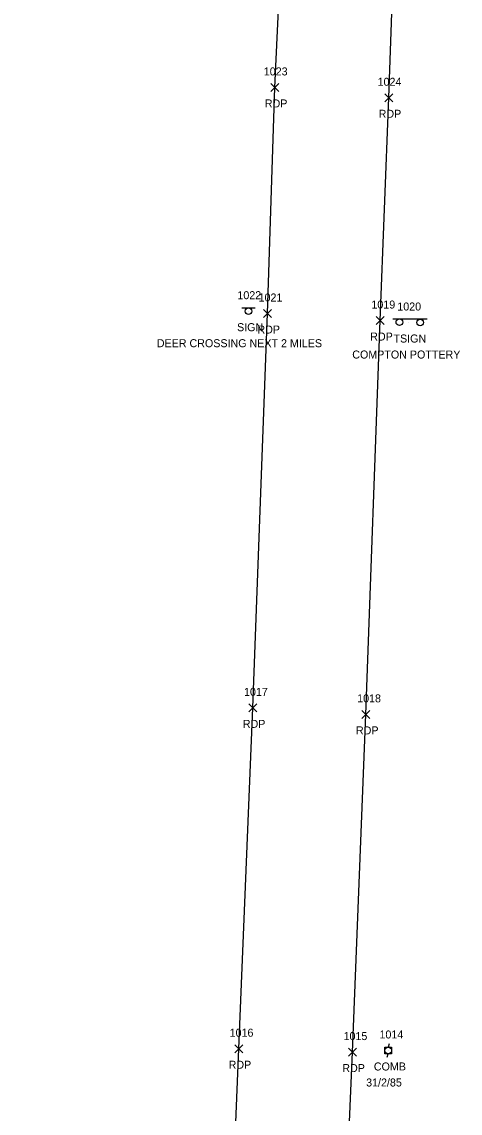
# Model space of a CAD drawing. Extents: x 1496556 to 1498241, y 599216 to 604470.
# Drawn here: x 1497213.5 to 1497323.1, y 602108 to 602380.7 of the extents above; entities that cross this region are included whole.
import ezdxf

# ---------------------------------------------------------------- set-up
doc = ezdxf.new("R2010")
doc.units = 0
for name, color, linetype in [('P_A', 7, 'Continuous'), ('P_I', 7, 'Continuous'), ('P_TIC', 7, 'Continuous'), ('PET', 7, 'Continuous'), ('S_A', 7, 'Continuous'), ('S_C', 7, 'Continuous'), ('S_I', 7, 'Continuous'), ('SSGN', 7, 'Continuous'), ('U_A', 7, 'Continuous'), ('U_C', 7, 'Continuous'), ('U_I', 7, 'Continuous'), ('UP', 7, 'Continuous')]:
    doc.layers.add(name, color=color, linetype=linetype)

msp = doc.modelspace()

# ---------------------------------------------------------------- linework, layer by layer
at = {"layer": 'P_TIC'}
for points in [[(1497275.81, 602363.31), (1497277.81, 602365.31)], [(1497277.81, 602363.31), (1497275.81, 602365.31)], [(1497304.27, 602360.72), (1497306.27, 602362.72)], [(1497306.27, 602360.72), (1497304.27, 602362.72)], [(1497273.95, 602306.82), (1497275.95, 602308.82)], [(1497275.95, 602306.82), (1497273.95, 602308.82)], [(1497302.16, 602305.06), (1497304.16, 602307.06)], [(1497304.16, 602305.06), (1497302.16, 602307.06)], [(1497270.3, 602208.29), (1497272.3, 602210.29)], [(1497272.3, 602208.29), (1497270.3, 602210.29)], [(1497298.59, 602206.66), (1497300.59, 602208.66)], [(1497300.59, 602206.66), (1497298.59, 602208.66)], [(1497266.76, 602123.12), (1497268.76, 602125.12)], [(1497268.76, 602123.12), (1497266.76, 602125.12)], [(1497295.19, 602122.28), (1497297.19, 602124.28)], [(1497297.19, 602122.28), (1497295.19, 602124.28)]]:
    msp.add_lwpolyline(points, dxfattribs=at)
at = {"layer": 'PET'}
for points in [[(1497255.35, 601840.33), (1497260.72, 601945.51), (1497260.6, 601945.5), (1497265.21, 602060.91), (1497267.76, 602124.12), (1497271.3, 602209.29), (1497274.95, 602307.82), (1497276.81, 602364.31), (1497278.84, 602406.87), (1497280.41, 602449.54), (1497282.45, 602505.14), (1497283.29, 602549.03), (1497283.31, 602599.78), (1497282.4, 602667.07), (1497280.87, 602701.36), (1497277.35, 602744.02), (1497266.99, 602833.93), (1497261.25, 602868.44), (1497249.2, 602924.4), (1497241.75, 602954.09), (1497234.18, 602981.9), (1497224.39, 603014.86), (1497221.77, 603020.8), (1497213.53, 603046.79)], [(1497283.3, 601836.85), (1497288.13, 601944.77), (1497293.47, 602059.45), (1497296.19, 602123.28), (1497299.59, 602207.66), (1497303.16, 602306.06), (1497305.27, 602361.72), (1497306.93, 602406.52), (1497308.5, 602446.65), (1497309.02, 602465.84), (1497310.76, 602505.51), (1497311.54, 602549.49), (1497311.88, 602599.1), (1497311.34, 602649.82), (1497308.95, 602706.57), (1497306.6, 602746.03), (1497301.66, 602792.87), (1497295.53, 602839.35), (1497290.13, 602872.5), (1497283.12, 602906.81), (1497277.08, 602932.51)]]:
    msp.add_lwpolyline(points, dxfattribs=at)
at = {"layer": 'SSGN'}
for p, q in [((1497268.58, 602309.25), (1497271.91, 602309.25)), ((1497270.23, 602308.42), (1497270.23, 602308.42)), ((1497306.27, 602306.49), (1497314.87, 602306.49)), ((1497310.3, 602305.59), (1497310.3, 602305.59))]:
    msp.add_line(p, q, dxfattribs=at)
for centre in [(1497270.23, 602308.42), (1497307.94, 602305.66), (1497313.15, 602305.59)]:
    msp.add_circle(centre, 0.833, dxfattribs=at)
at = {"layer": 'UP'}
for p, q in [((1497304.34, 602122.84), (1497304.34, 602124.51)), ((1497304.34, 602124.51), (1497306, 602124.51)), ((1497305.42, 602125.34), (1497305.17, 602124.51)), ((1497305.17, 602123.68), (1497305.17, 602123.68)), ((1497306, 602124.51), (1497306, 602122.84)), ((1497306, 602122.84), (1497304.34, 602122.84)), ((1497304.92, 602122.01), (1497305.17, 602122.84))]:
    msp.add_line(p, q, dxfattribs=at)
msp.add_circle((1497305.17, 602123.68), 0.833, dxfattribs=at)

# ---------------------------------------------------------------- texts
at = {"layer": 'P_A'}
for p in [(1497274.3, 602359.31), (1497302.76, 602356.72), (1497272.44, 602302.82), (1497300.65, 602301.06), (1497268.79, 602204.29), (1497297.08, 602202.66), (1497265.25, 602119.12), (1497293.67, 602118.28)]:
    msp.add_text('RDP', height=2, dxfattribs=at).set_placement(p)
at = {"layer": 'P_I'}
for s, p in [('1023', (1497274.04, 602367.31)), ('1024', (1497302.5, 602364.72)), ('1021', (1497272.74, 602310.82)), ('1019', (1497300.95, 602309.06)), ('1017', (1497269.1, 602212.29)), ('1018', (1497297.39, 602210.66)), ('1016', (1497265.5, 602127.12)), ('1015', (1497293.98, 602126.28))]:
    msp.add_text(s, height=2, dxfattribs=at).set_placement(p)
at = {"layer": 'S_A'}
for s, p in [('SIGN', (1497267.36, 602303.4)), ('TSIGN', (1497306.47, 602300.57))]:
    msp.add_text(s, height=2, dxfattribs=at).set_placement(p)
at = {"layer": 'S_C'}
for s, p in [('DEER CROSSING NEXT 2 MILES', (1497247.29, 602299.4)), ('COMPTON POTTERY', (1497296.16, 602296.57))]:
    msp.add_text(s, height=2, dxfattribs=at).set_placement(p)
at = {"layer": 'S_I'}
for s, p in [('1022', (1497267.44, 602311.4)), ('1020', (1497307.43, 602308.57))]:
    msp.add_text(s, height=2, dxfattribs=at).set_placement(p)
at = {"layer": 'U_A'}
msp.add_text('COMB', height=2, dxfattribs=at).set_placement((1497301.56, 602118.68))
at = {"layer": 'U_C'}
msp.add_text('31/2/85', height=2, dxfattribs=at).set_placement((1497299.63, 602114.68))
at = {"layer": 'U_I'}
msp.add_text('1014', height=2, dxfattribs=at).set_placement((1497302.97, 602126.68))

doc.saveas('drawing.dxf')
